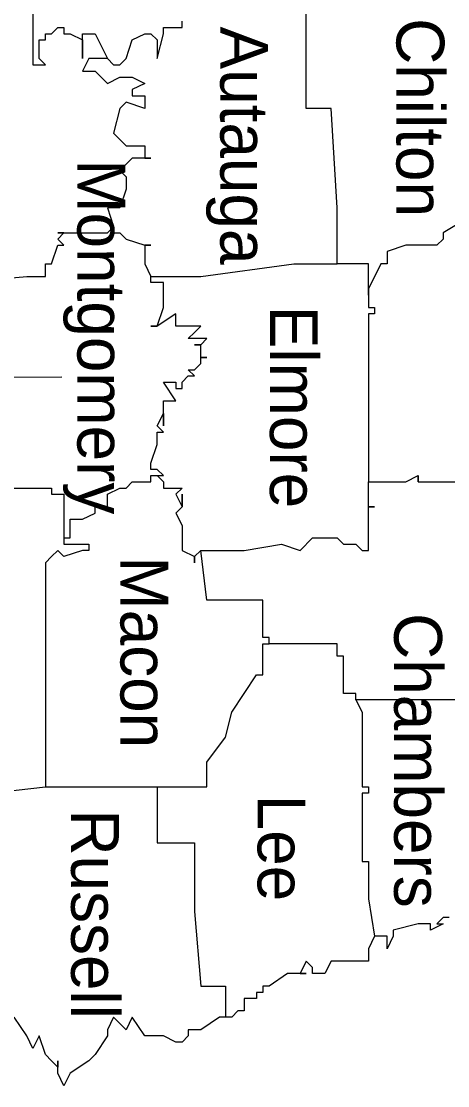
# Model space of a CAD drawing. Extents: x 0 to 0.917, y 0 to 0.708.
# Drawn here: x 0.4398 to 0.4862, y 0.4261 to 0.5421 of the extents above; entities that cross this region are included whole.
import ezdxf

# ---------------------------------------------------------------- set-up
doc = ezdxf.new("R2010")
doc.units = 0
doc.layers.add('ANNO-SHT', color=7, linetype='Continuous')
doc.layers.add('ANNO-TXT', color=7, linetype='Continuous')

msp = doc.modelspace()

# ---------------------------------------------------------------- linework, layer by layer
at = {"layer": 'ANNO-SHT'}
msp.add_line((0.44418, 0.5033), (0.34372, 0.50284), dxfattribs=at)
for points in [[(0.44102, 0.54347), (0.44102, 0.53736), (0.44237, 0.53736), (0.44169, 0.53804), (0.44169, 0.53804), (0.44169, 0.53804), (0.44169, 0.54008), (0.44237, 0.54008), (0.44237, 0.54075), (0.44237, 0.54075), (0.44237, 0.54075), (0.44305, 0.54075), (0.44305, 0.54075), (0.44372, 0.54143), (0.4444, 0.54143), (0.4444, 0.54075), (0.4444, 0.54075), (0.44508, 0.54075), (0.44508, 0.54075), (0.44508, 0.54075), (0.44508, 0.54075), (0.44643, 0.54008), (0.44643, 0.54008), (0.44643, 0.54008), (0.44643, 0.53804), (0.44643, 0.54008), (0.44643, 0.54075), (0.44778, 0.54075), (0.44914, 0.53804)], [(0.47756, 0.51293), (0.47756, 0.51225), (0.47756, 0.51564), (0.47417, 0.51564), (0.47417, 0.51904), (0.47417, 0.51971), (0.47417, 0.52175), (0.4735, 0.53261), (0.47079, 0.53261), (0.47079, 0.53533), (0.47079, 0.53804), (0.47079, 0.54415)], [(0.44914, 0.53804), (0.44981, 0.53736), (0.45049, 0.53736), (0.45117, 0.53804), (0.45184, 0.54008), (0.4532, 0.54075), (0.45387, 0.54075), (0.45455, 0.54008), (0.45455, 0.53804), (0.45455, 0.53804), (0.45523, 0.54075), (0.45523, 0.54075), (0.45523, 0.54143), (0.45658, 0.54143), (0.45726, 0.54143), (0.45726, 0.54211)], [(0.44914, 0.53804), (0.44711, 0.53804), (0.44711, 0.53804), (0.44643, 0.53668), (0.44711, 0.53668), (0.44778, 0.53668), (0.44914, 0.53533), (0.45049, 0.536), (0.45184, 0.536), (0.4532, 0.53533), (0.45184, 0.53465), (0.45184, 0.53397), (0.4532, 0.53397), (0.4532, 0.53397), (0.4532, 0.53261), (0.45117, 0.53329), (0.45049, 0.53261), (0.44981, 0.5299), (0.45117, 0.52854), (0.4532, 0.52854), (0.4532, 0.52854), (0.4532, 0.52718), (0.45387, 0.52718), (0.4532, 0.52718), (0.45184, 0.52718), (0.45184, 0.52718), (0.45049, 0.52582), (0.45117, 0.52514), (0.45117, 0.52379), (0.45049, 0.52175), (0.44914, 0.52175), (0.44914, 0.52175), (0.44981, 0.51971)], [(0.49515, 0.52107), (0.49312, 0.52107), (0.49244, 0.52107), (0.49109, 0.52107), (0.48974, 0.52107), (0.48906, 0.52107), (0.48568, 0.51904), (0.48568, 0.51836), (0.485, 0.51768), (0.48432, 0.51768), (0.48432, 0.51768), (0.48162, 0.51768), (0.47959, 0.517), (0.47959, 0.51564), (0.47891, 0.51564), (0.47756, 0.51293)], [(0.49515, 0.52107), (0.49312, 0.52107), (0.49244, 0.52107), (0.49109, 0.52107), (0.48974, 0.52107), (0.48906, 0.52107), (0.48568, 0.51904), (0.48568, 0.51836), (0.485, 0.51768), (0.48432, 0.51768), (0.48432, 0.51768), (0.48162, 0.51768), (0.47959, 0.517), (0.47959, 0.51564), (0.47891, 0.51564), (0.47756, 0.51293)], [(0.4329, 0.51361), (0.44034, 0.51428), (0.44237, 0.51428), (0.44237, 0.51428), (0.44237, 0.51428), (0.44237, 0.51564), (0.44305, 0.51564), (0.44372, 0.51768), (0.4444, 0.51768), (0.44372, 0.51836), (0.44372, 0.51836), (0.4444, 0.51904), (0.44372, 0.51904), (0.4444, 0.51904), (0.4444, 0.51904), (0.4444, 0.51904), (0.44508, 0.51904), (0.44508, 0.51904), (0.44508, 0.51904), (0.44508, 0.51904), (0.44643, 0.51904), (0.44643, 0.51904), (0.44643, 0.51904), (0.44711, 0.51904), (0.44711, 0.51904), (0.44711, 0.51904), (0.44778, 0.51904), (0.44778, 0.51904), (0.44778, 0.51904), (0.44778, 0.51904), (0.44778, 0.51904), (0.44778, 0.51904), (0.44914, 0.51904), (0.44914, 0.51904), (0.44914, 0.51904), (0.44914, 0.51904), (0.44981, 0.51971), (0.44981, 0.51904), (0.44981, 0.51904), (0.45049, 0.51904), (0.45049, 0.51904), (0.45117, 0.51836), (0.4532, 0.51768), (0.45387, 0.51768), (0.4532, 0.51768), (0.4532, 0.51564), (0.45387, 0.51428)], [(0.45455, 0.49257), (0.45523, 0.49257), (0.45455, 0.49324), (0.45455, 0.49324), (0.45387, 0.49324), (0.45387, 0.49392), (0.45455, 0.49596), (0.45455, 0.49596), (0.45455, 0.49732), (0.45455, 0.49732), (0.45455, 0.49732), (0.45523, 0.49732), (0.45455, 0.498), (0.45523, 0.49935), (0.45523, 0.498), (0.45523, 0.49935), (0.45523, 0.49935), (0.45523, 0.49935), (0.45523, 0.50003), (0.45523, 0.50071), (0.45658, 0.50071), (0.45523, 0.50275), (0.45658, 0.50275), (0.45658, 0.50207), (0.45726, 0.50207), (0.45726, 0.50275), (0.45726, 0.50275), (0.45726, 0.50275), (0.45793, 0.50343), (0.45861, 0.50343), (0.45793, 0.5041), (0.45793, 0.5041), (0.45861, 0.5041), (0.45861, 0.5041), (0.45929, 0.50478), (0.45929, 0.50478), (0.45929, 0.50478), (0.45929, 0.50546), (0.45996, 0.50546), (0.45929, 0.50546), (0.45929, 0.50682), (0.45861, 0.50682), (0.45929, 0.50682), (0.45996, 0.5075), (0.45996, 0.5075), (0.45861, 0.5075), (0.45793, 0.5075), (0.45861, 0.50818), (0.45929, 0.50886), (0.45929, 0.50886), (0.45861, 0.50886), (0.45861, 0.50886), (0.45726, 0.50886), (0.45658, 0.50886), (0.45658, 0.51021), (0.45658, 0.51021), (0.45455, 0.50886), (0.45387, 0.50886), (0.45387, 0.50886), (0.45455, 0.50886), (0.45455, 0.50886), (0.45523, 0.51089), (0.45523, 0.51089), (0.45523, 0.51157), (0.45523, 0.51157), (0.45523, 0.51225), (0.45523, 0.51225), (0.45523, 0.51361), (0.45523, 0.51361), (0.45455, 0.51361), (0.45455, 0.51361), (0.45387, 0.51361), (0.45387, 0.51428), (0.45387, 0.51428), (0.45455, 0.51428), (0.45861, 0.51428), (0.45929, 0.51428), (0.46944, 0.51564), (0.47011, 0.51564), (0.47417, 0.51564)], [(0.47756, 0.51293), (0.47756, 0.51089), (0.47823, 0.51089), (0.47823, 0.51021), (0.47756, 0.51021), (0.47756, 0.50478), (0.47756, 0.49732), (0.47756, 0.49189)], [(0.47756, 0.51293), (0.47756, 0.51089), (0.47823, 0.51089), (0.47823, 0.51021), (0.47756, 0.51021), (0.47756, 0.50478), (0.47756, 0.49732), (0.47756, 0.49189)], [(0.47756, 0.49189), (0.48162, 0.49189), (0.48297, 0.49257), (0.48297, 0.49189), (0.48297, 0.49189), (0.48297, 0.49257), (0.48297, 0.49257), (0.48297, 0.49189), (0.48703, 0.49189), (0.48771, 0.49189), (0.49244, 0.49257), (0.50056, 0.49257), (0.50124, 0.49257), (0.50124, 0.49257), (0.50124, 0.50207)], [(0.4444, 0.48578), (0.44508, 0.48578), (0.44508, 0.48781), (0.44643, 0.48781), (0.44778, 0.48849), (0.44778, 0.48849), (0.44778, 0.48917), (0.44914, 0.48917), (0.44914, 0.49053), (0.45049, 0.49121), (0.45117, 0.49121), (0.45184, 0.49189), (0.45184, 0.49189), (0.4532, 0.49189), (0.4532, 0.49189), (0.45387, 0.49189), (0.45387, 0.49189), (0.45387, 0.49257), (0.45455, 0.49257), (0.45455, 0.49257), (0.45523, 0.49189), (0.45523, 0.49121), (0.45658, 0.49121), (0.45726, 0.49121), (0.45658, 0.49053), (0.45658, 0.49053), (0.45726, 0.48917), (0.45726, 0.49053), (0.45726, 0.48917), (0.45658, 0.48849), (0.45726, 0.48714), (0.45726, 0.4851), (0.45726, 0.48442), (0.45726, 0.48442), (0.45726, 0.48442), (0.45861, 0.48374), (0.45861, 0.48306), (0.45861, 0.48306), (0.45861, 0.48374), (0.45929, 0.48442)], [(0.42951, 0.49121), (0.4356, 0.49121), (0.44305, 0.49121), (0.44305, 0.49053), (0.4444, 0.49053), (0.4444, 0.49053), (0.4444, 0.48578), (0.4444, 0.4851), (0.44711, 0.4851), (0.44711, 0.48442), (0.44643, 0.48442), (0.44643, 0.48442), (0.4444, 0.48374), (0.44372, 0.48442), (0.44305, 0.48374), (0.44305, 0.48374), (0.44237, 0.48306), (0.44237, 0.48306), (0.44237, 0.47492), (0.44237, 0.45863)], [(0.46673, 0.47424), (0.46673, 0.47492), (0.46605, 0.47492), (0.46605, 0.47696), (0.46605, 0.47899), (0.46402, 0.47899), (0.45996, 0.47899), (0.45996, 0.47899), (0.45929, 0.48442), (0.46132, 0.48442), (0.46267, 0.48442), (0.46402, 0.48442), (0.46808, 0.4851), (0.47011, 0.48442), (0.47147, 0.48578), (0.47282, 0.48578), (0.47417, 0.48578), (0.47417, 0.48578), (0.47485, 0.4851), (0.47485, 0.4851), (0.4762, 0.4851), (0.47688, 0.48442), (0.47756, 0.48442), (0.47756, 0.48849), (0.47756, 0.48917), (0.47823, 0.48917), (0.47823, 0.48917), (0.47756, 0.48917), (0.47756, 0.49189)], [(0.46673, 0.47424), (0.46673, 0.47492), (0.46605, 0.47492), (0.46605, 0.47696), (0.46605, 0.47899), (0.46402, 0.47899), (0.45996, 0.47899), (0.45996, 0.47899), (0.45929, 0.48442), (0.46132, 0.48442), (0.46267, 0.48442), (0.46402, 0.48442), (0.46808, 0.4851), (0.47011, 0.48442), (0.47147, 0.48578), (0.47282, 0.48578), (0.47417, 0.48578), (0.47417, 0.48578), (0.47485, 0.4851), (0.47485, 0.4851), (0.4762, 0.4851), (0.47688, 0.48442), (0.47756, 0.48442), (0.47756, 0.48849), (0.47756, 0.48917), (0.47823, 0.48917), (0.47823, 0.48917), (0.47756, 0.48917), (0.47756, 0.49189)], [(0.45455, 0.45863), (0.45658, 0.45863), (0.45996, 0.45863), (0.45996, 0.46134), (0.46199, 0.46406), (0.46267, 0.46677), (0.46538, 0.47085), (0.46538, 0.47085), (0.46605, 0.47085), (0.46605, 0.47424), (0.46673, 0.47424)], [(0.45455, 0.45863), (0.45658, 0.45863), (0.45996, 0.45863), (0.45996, 0.46134), (0.46199, 0.46406), (0.46267, 0.46677), (0.46538, 0.47085), (0.46538, 0.47085), (0.46605, 0.47085), (0.46605, 0.47424), (0.46673, 0.47424)], [(0.4762, 0.46813), (0.4762, 0.46881), (0.47485, 0.46881), (0.47485, 0.47288), (0.47417, 0.47288), (0.47417, 0.47424), (0.46673, 0.47424)], [(0.50192, 0.47085), (0.50192, 0.46813), (0.50124, 0.46813), (0.48297, 0.46813), (0.4762, 0.46813)], [(0.4762, 0.46813), (0.47688, 0.46677), (0.47688, 0.46677), (0.47688, 0.46677), (0.47688, 0.46677), (0.47688, 0.46677), (0.47688, 0.46677), (0.47688, 0.4627), (0.47688, 0.46202), (0.47688, 0.46202), (0.47688, 0.46134), (0.47688, 0.46134), (0.47688, 0.45863), (0.47756, 0.45863), (0.47756, 0.45863), (0.47756, 0.45795), (0.47756, 0.45795), (0.47688, 0.45795), (0.47688, 0.45592), (0.47688, 0.45592), (0.47688, 0.45592), (0.47688, 0.45592), (0.47688, 0.45049), (0.47688, 0.45049), (0.47756, 0.45049), (0.47756, 0.44641), (0.47823, 0.44234)], [(0.43628, 0.45592), (0.43628, 0.45795), (0.44237, 0.45863), (0.44237, 0.45863), (0.44372, 0.45863), (0.45455, 0.45863)], [(0.43628, 0.45795), (0.44237, 0.45863), (0.44237, 0.45863), (0.44372, 0.45863), (0.45455, 0.45863)], [(0.45455, 0.45863), (0.45455, 0.4532), (0.45455, 0.45252), (0.45726, 0.45252), (0.45861, 0.45252), (0.45861, 0.44506), (0.45929, 0.43691), (0.46199, 0.43691), (0.46199, 0.43691), (0.46199, 0.43352)], [(0.48635, 0.44438), (0.48568, 0.44438), (0.48568, 0.44438), (0.485, 0.4437), (0.48568, 0.4437), (0.48432, 0.44302), (0.48432, 0.4437), (0.48365, 0.4437), (0.48365, 0.4437), (0.48297, 0.4437), (0.48026, 0.44302), (0.48026, 0.44234), (0.48026, 0.44234), (0.47959, 0.44098), (0.47959, 0.44098), (0.47959, 0.44234), (0.47959, 0.44234), (0.47891, 0.44234), (0.47891, 0.44234), (0.47823, 0.44234)], [(0.47823, 0.44234), (0.47756, 0.44098), (0.47756, 0.43963), (0.47688, 0.43963), (0.4762, 0.43963), (0.4762, 0.43963), (0.47485, 0.43963), (0.4735, 0.43963), (0.47282, 0.43827), (0.47282, 0.43827), (0.47147, 0.43827), (0.47147, 0.43895), (0.47079, 0.43963), (0.47011, 0.43827), (0.47079, 0.43827), (0.47011, 0.43827), (0.47011, 0.43827), (0.46944, 0.43827), (0.46944, 0.43827), (0.46876, 0.43827), (0.46876, 0.43827), (0.46673, 0.43691), (0.46605, 0.43691), (0.46605, 0.43623), (0.46538, 0.43623), (0.46538, 0.43555), (0.46402, 0.43555), (0.46402, 0.4342), (0.46402, 0.4342), (0.46335, 0.4342), (0.46267, 0.43352), (0.46267, 0.43352), (0.46267, 0.43352), (0.46199, 0.43352), (0.46132, 0.43352), (0.45929, 0.43216), (0.45793, 0.43216), (0.45793, 0.43148), (0.45726, 0.4308), (0.45658, 0.4308), (0.45523, 0.43148), (0.45455, 0.43148), (0.45387, 0.43148), (0.45387, 0.43148), (0.4532, 0.43148), (0.4532, 0.43148), (0.45184, 0.43352), (0.45117, 0.43216), (0.44981, 0.43352), (0.44914, 0.43216), (0.44914, 0.43148), (0.44778, 0.42945), (0.44711, 0.42877), (0.44508, 0.42741), (0.4444, 0.42605), (0.44372, 0.42741), (0.44372, 0.42877), (0.44372, 0.42809), (0.44305, 0.42877), (0.44237, 0.42945), (0.44169, 0.43148), (0.44102, 0.43012), (0.44034, 0.43148), (0.43899, 0.43352)]]:
    msp.add_lwpolyline(points, dxfattribs=at)

# ---------------------------------------------------------------- texts
at = {"layer": 'ANNO-TXT'}
for s, p in [('Chilton', (0.48061, 0.54244)), ('Autauga', (0.46142, 0.54153)), ('Montgomery', (0.44586, 0.52705)), ('Elmore', (0.46683, 0.51107)), ('Macon', (0.45055, 0.48375)), ('Chambers', (0.48036, 0.47758)), ('Lee', (0.46549, 0.45778)), ('Russell', (0.44518, 0.45617))]:
    msp.add_text(s, height=0.005208, rotation=270, dxfattribs=at).set_placement(p)

doc.saveas('drawing.dxf')
